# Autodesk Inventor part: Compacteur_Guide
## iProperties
Created: 2008-12
Part Number: Compacteur_Guide
Document SubType Name: Modeling
Designer: claivier
Material: Acier galvanisé
MajorVersion: 11
MinorVersion: 1
Author: claivier
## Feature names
1. Extrusion1
2. Extrusion2
3. Extrusion3
4. Extrusion4
5. Perçage1 [Hole]
6. Extrusion5
7. Chanfrein1 [Chamfer]
8. Miroir1 [Mirror]
9. Perçage2 [Hole]
10. Extrusion6
11. Perçage3 [Hole]
12. Miroir2 [Mirror]
